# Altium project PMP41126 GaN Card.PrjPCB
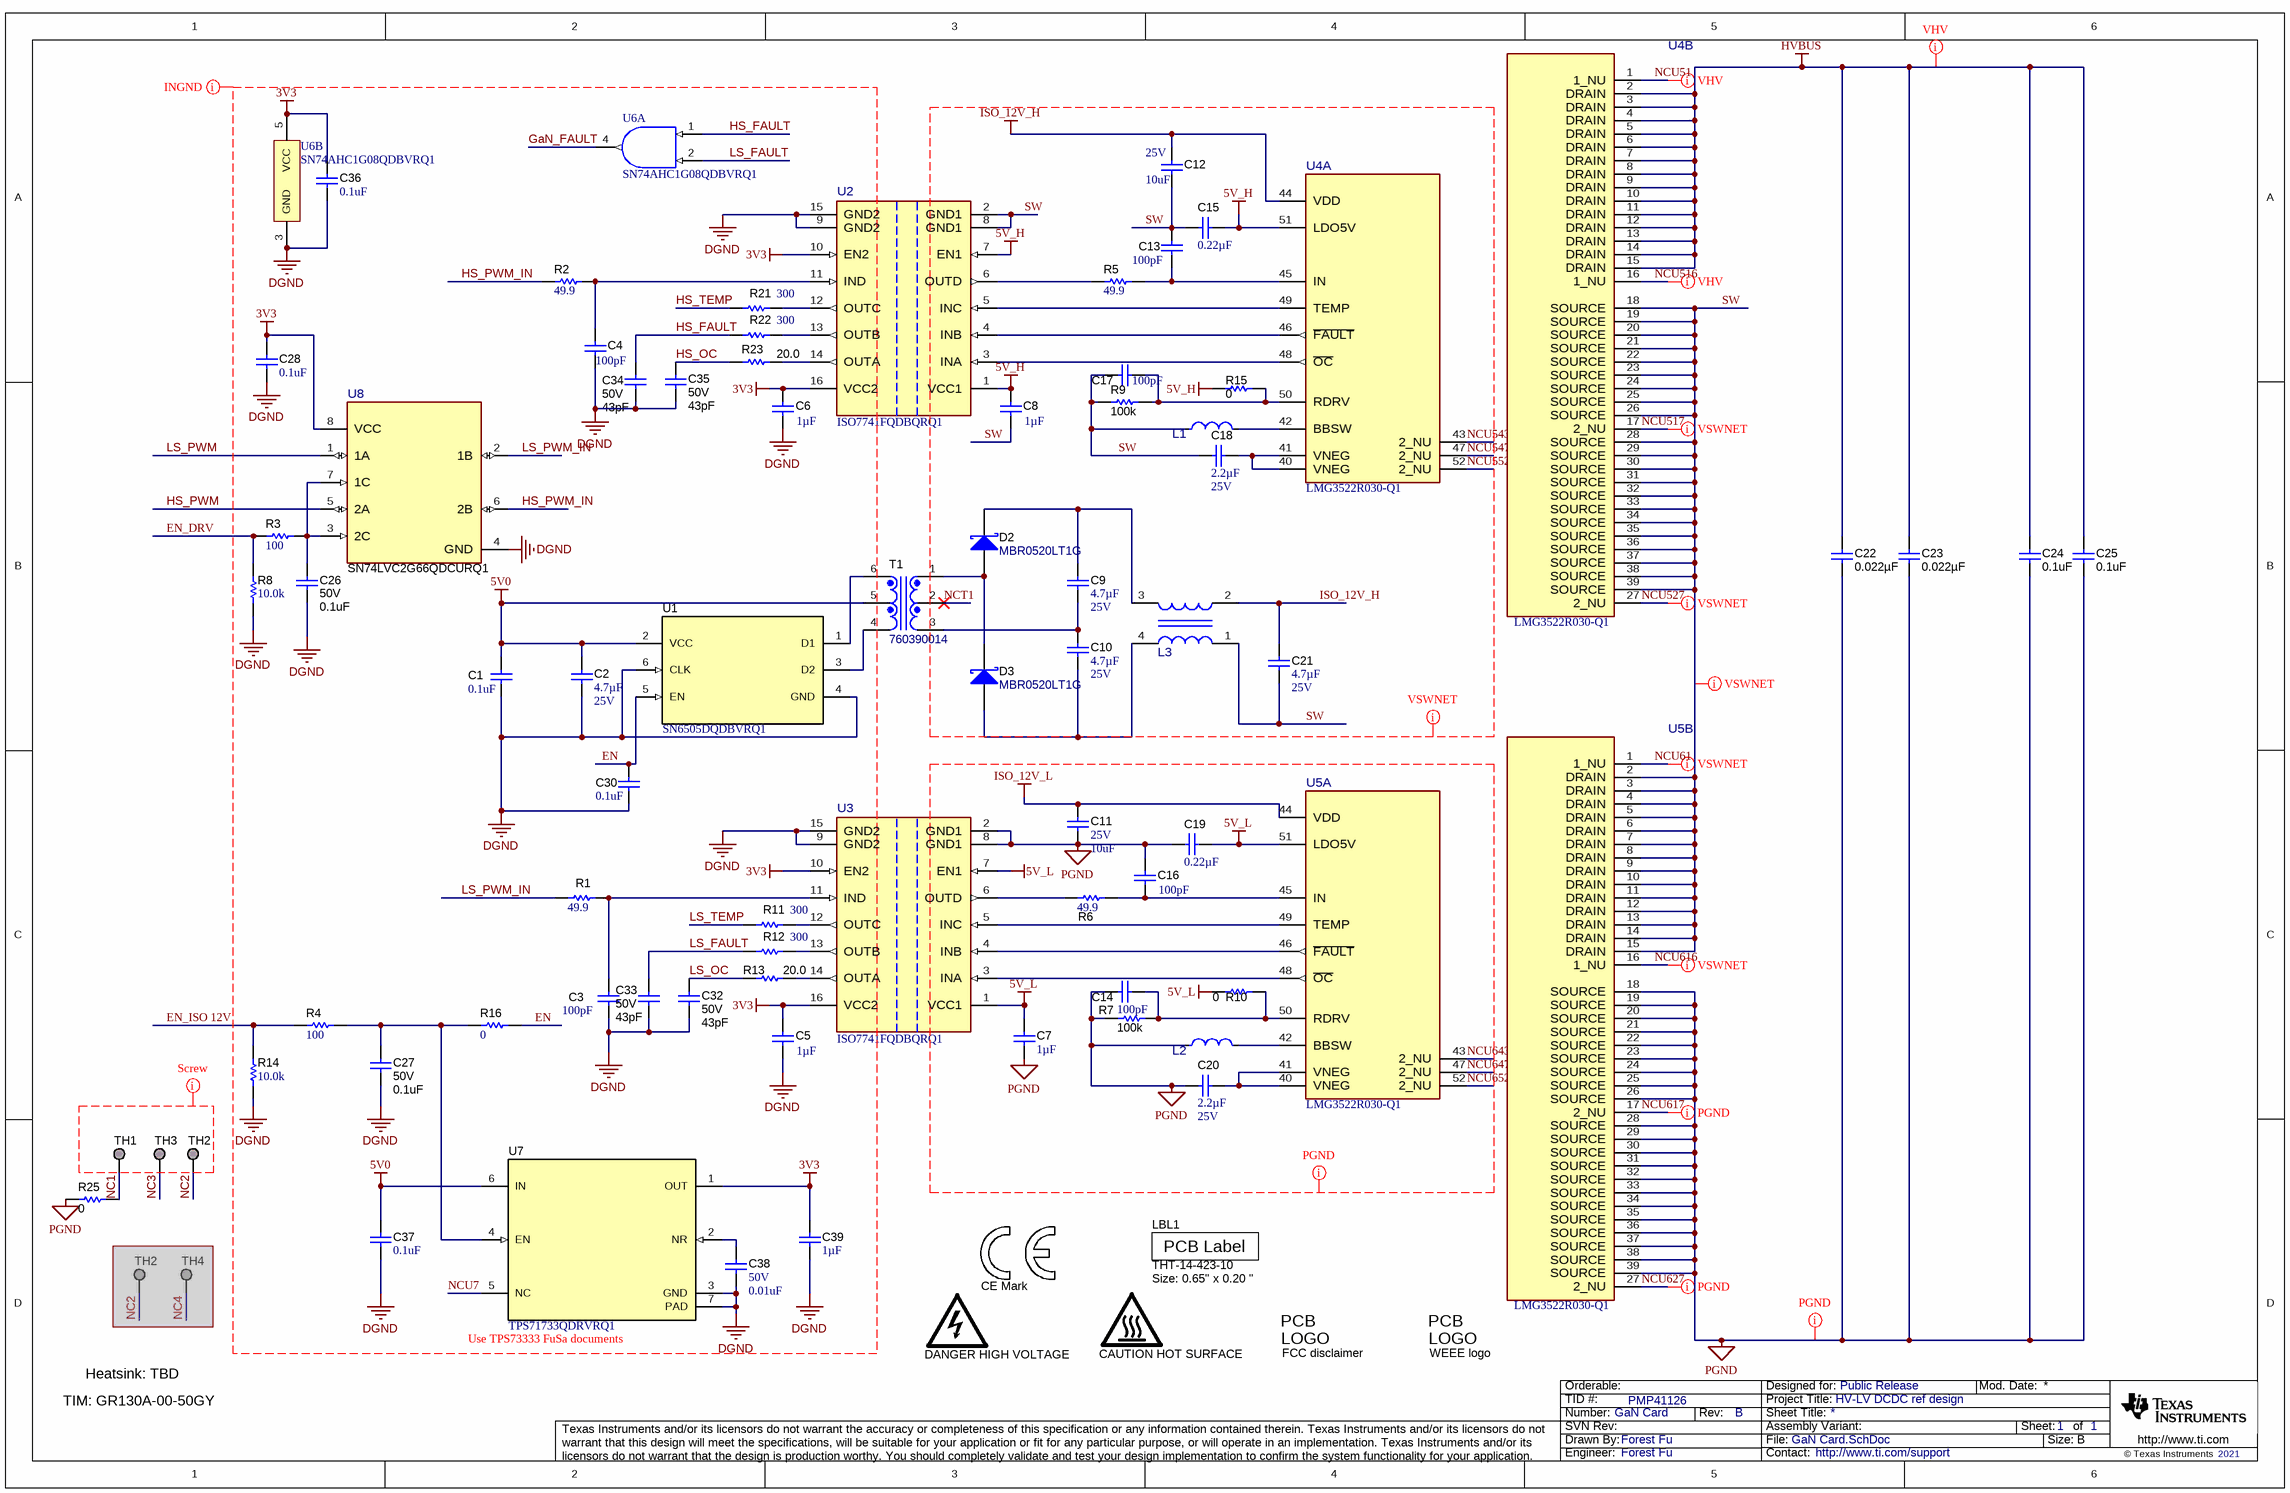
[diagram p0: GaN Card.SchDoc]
CopyrightYear: 2021; PCB_Layout: Forest Fu; PCB_Rev: B; PRJ_Customer: Public Release; PRJ_Engineer: Forest Fu; PRJ_Number: GaN Card; PRJ_Title: HV-LV DCDC ref design; SCH_Rev: B; TechSupport: http://www.ti.com/support; TID: PMP41126
2 sheets, 90 parts. Net scope: global (net labels, ports and power ports of the same name join across sheets).
Board file: GaN Card.PcbDoc
Sheets:
  GaN Card.SchDoc
  GaN Card_Hardware.SchDoc

## Sheet GaN Card.SchDoc
size 431 x 279 mm; DrawnBy: Forest Fu; SheetNumber: 1; SheetTotal: 1; PageSetup: Record=PageOptions¦CenterHorizontal=True¦CenterVertical=True¦PrintScale=1.00¦XCorrection=1.00¦YCorrection=1.00¦PrintKind=0¦BorderSize=5000000¦LeftOffset=0¦BottomOffset=0¦Orientation=2¦PaperLength=1000¦PaperWidth=1000¦Scale=100¦PaperSource=15¦PrintQuality=600¦MediaType=1¦DitherType=10¦PaperKind=Letter¦PrintScaleMode=1

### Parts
(Parts that share a designator on the sheet are numbered #1, #2 ... from top to bottom, then left to right.)
C1  ValueDisplayed: 0.1uF  [0402]  (hidden comment: GCM155R71H104KE02D)
C2  Cap_F: 4.7µF  VDC_V: 25V  [0805]  (hidden comment: CGA4J1X7R1E475K125AC)
C3  ValueDisplayed: 100pF  [0402]  (hidden comment: CGA2B2C0G1H101J050BA)
C4  ValueDisplayed: 100pF  [0402]  (hidden comment: CGA2B2C0G1H101J050BA)
C5  ValueDisplayed: 1µF  [0402]  (hidden comment: GRT155C71A105KE13D)
C6  ValueDisplayed: 1µF  [0402]  (hidden comment: GRT155C71A105KE13D)
C7  ValueDisplayed: 1µF  [0402]  (hidden comment: GRT155C71A105KE13D)
C8  ValueDisplayed: 1µF  [0402]  (hidden comment: GRT155C71A105KE13D)
C9  Cap_F: 4.7µF  VDC_V: 25V  [0805L]  (hidden comment: CGA4J1X7R1E475K125AC)
C10  Cap_F: 4.7µF  VDC_V: 25V  [0805L]  (hidden comment: CGA4J1X7R1E475K125AC)
C11  VDC_V: 25V  ValueDisplayed: 10uF  [1206_190]  (hidden comment: GCM31CC71E106KA03L)
C12  VDC_V: 25V  ValueDisplayed: 10uF  [1206_190]  (hidden comment: GCM31CC71E106KA03L)
C13  ValueDisplayed: 100pF  [0402]  (hidden comment: CGA2B2C0G1H101J050BA)
C14  ValueDisplayed: 100pF  [0402]  (hidden comment: CGA2B2C0G1H101J050BA)
C15  ValueDisplayed: 0.22µF  [0402]  (hidden comment: GCM155R71C224KE02D)
C16  ValueDisplayed: 100pF  [0402]  (hidden comment: CGA2B2C0G1H101J050BA)
C17  ValueDisplayed: 100pF  [0402]  (hidden comment: CGA2B2C0G1H101J050BA)
C18  Cap_F: 2.2µF  VDC_V: 25V  [0805_HV]  (hidden comment: GCM21BR71E225KA73L)
C19  ValueDisplayed: 0.22µF  [0402]  (hidden comment: GCM155R71C224KE02D)
C20  Cap_F: 2.2µF  VDC_V: 25V  [0805_HV]  (hidden comment: GCM21BR71E225KA73L)
C21  Cap_F: 4.7µF  VDC_V: 25V  [0805L]  (hidden comment: CGA4J1X7R1E475K125AC)
C22  ValueDisplayed: 0.022µF  [1206_190]  (hidden comment: C1206C223KDRACTU)
C23  ValueDisplayed: 0.022µF  [1206_190]  (hidden comment: C1206C223KDRACTU)
C24  ValueDisplayed: 0.1uF  [1812_254]  (hidden comment: C1812W104KDRACTU)
C25  ValueDisplayed: 0.1uF  [1812_254]  (hidden comment: C1812W104KDRACTU)
C26  VDC_V: 50V  ValueDisplayed: 0.1uF  [0402]  (hidden comment: GCM155R71H104KE02D)
C27  VDC_V: 50V  ValueDisplayed: 0.1uF  [0402]  (hidden comment: GCM155R71H104KE02D)
C28  ValueDisplayed: 0.1uF  [0402]  (hidden comment: GCM155R71H104KE02D)
C30  ValueDisplayed: 0.1uF  [0402]  (hidden comment: GCM155R71H104KE02D)
C32  VDC_V: 50V  ValueDisplayed: 43pF  [0402]  (hidden comment: GCQ1555C1H430JB01D)
C33  VDC_V: 50V  ValueDisplayed: 43pF  [0402]  (hidden comment: GCQ1555C1H430JB01D)
C34  VDC_V: 50V  ValueDisplayed: 43pF  [0402]  (hidden comment: GCQ1555C1H430JB01D)
C35  VDC_V: 50V  ValueDisplayed: 43pF  [0402]  (hidden comment: GCQ1555C1H430JB01D)
C36  ValueDisplayed: 0.1uF  [0402]  (hidden comment: GCM155R71H104KE02D)
C37  ValueDisplayed: 0.1uF  [0402]  (hidden comment: GCM155R71H104KE02D)
C38  VDC_V: 50V  ValueDisplayed: 0.01uF  [0402]  (hidden comment: CGA2B3X7R1H103K050BB)
C39  ValueDisplayed: 1µF  [0402]  (hidden comment: GRT155C71A105KE13D)
CAUTION_HOT_SURFACE  CAUTION HOT SURFACE  [IEC_HotSurface_Small]  (no BOM)
D2  MBR0520LT1G  [SOD-123]
D3  MBR0520LT1G  [SOD-123]
DANGER_HIGH_VOLTAGE  DANGER HIGH VOLTAGE  [IEC_HighVoltage_Small]  (no BOM)
L1  SDEM20161T-4R7MS  [FP-SDEM20161T-4R7MS_SMD2-MFG]  (value not drawn)
L2  SDEM20161T-4R7MS  [FP-SDEM20161T-4R7MS_SMD2-MFG]  (value not drawn)
L3  ACT32P-102-2P-TL01  [FP-ACT32P-102-2P-TL01_SMT4_3MM9_2MM5-MFG]  (value not drawn)
LBL1  THT-14-423-10  Note: Size: 0.65" x 0.20 "  [Label_650x200]
Logo1  CE Mark  [CE_Mark_5mm]  (no BOM)
Logo3  FCC disclaimer  [FCC_disclaimer]  (no BOM)
Logo4  WEEE logo  [WEEE_Minimum]  (no BOM)
R1  ValueDisplayed: 49.9  [0402]  (hidden comment: CRCW040249R9FKED)
R2  ValueDisplayed: 49.9  [0402]  (hidden comment: CRCW040249R9FKED)
R3  ValueDisplayed: 100  [0402]  (hidden comment: CRCW0402100RFKED)
R4  ValueDisplayed: 100  [0402]  (hidden comment: CRCW0402100RFKED)
R5  ValueDisplayed: 49.9  [0402]  (hidden comment: CRCW040249R9FKED)
R6  ValueDisplayed: 49.9  [0402]  (hidden comment: CRCW040249R9FKED)
R7  ValueDisplayed: 100k  [0402]  (hidden comment: CRCW0402100KFKED)
R8  ValueDisplayed: 10.0k  [0402]  (hidden comment: MCS0402MD1002BE100)
R9  ValueDisplayed: 100k  [0402]  (hidden comment: CRCW0402100KFKED)
R10  ValueDisplayed: 0  [0402]  (hidden comment: ERJ-2GE0R00X)
R11  ValueDisplayed: 300  [0402]  (hidden comment: CRCW0402300RJNED)
R12  ValueDisplayed: 300  [0402]  (hidden comment: CRCW0402300RJNED)
R13  ValueDisplayed: 20.0  [0402]  (hidden comment: CRCW040220R0FKED)
R14  ValueDisplayed: 10.0k  [0402]  (hidden comment: MCS0402MD1002BE100)
R15  ValueDisplayed: 0  [0402]  (hidden comment: ERJ-2GE0R00X)
R16  ValueDisplayed: 0  [0402]  (hidden comment: CRCW04020000Z0EDHP)
R21  ValueDisplayed: 300  [0402]  (hidden comment: CRCW0402300RJNED)
R22  ValueDisplayed: 300  [0402]  (hidden comment: CRCW0402300RJNED)
R23  ValueDisplayed: 20.0  [0402]  (hidden comment: CRCW040220R0FKED)
R25  ValueDisplayed: 0  [1206]  (hidden comment: CRCW12060000Z0EA)
T1  760390014  [Wurth_760390013]
TH1  (no value)  [TP_H045P075]  (no BOM)
TH2#1  (no value)  [TP_H045P075]  (no BOM)
TH2#2  (no value)  [TP_H045P075]  (no BOM)  (masked out: inside a compile mask, not in the netlist)
TH3  (no value)  [TP_H045P075]  (no BOM)
TH4  (no value)  [TP_H045P075]  (no BOM)  (masked out: inside a compile mask, not in the netlist)
U1  SN6505DQDBVRQ1  [DBV0006A_N]
U2  ISO7741FQDBQRQ1  [DBQ0016A-MFG]
U3  ISO7741FQDBQRQ1  [DBQ0016A-MFG]
U4  LMG3522R030-Q1  [RQS0052C-C01-MFG]  (parts A,B of 2)
U5  LMG3522R030-Q1  [RQS0052C-C01-MFG]  (parts A,B of 2)
U6  SN74AHC1G08QDBVRQ1  [DBV0005A_N]  (parts A,B of 2)
U7  TPS71733QDRVRQ1  [DRV0006A]
U8  SN74LVC2G66QDCURQ1  [DCU0008A-MFG]

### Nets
3V3: C5.1 C6.1 C28.1 C36.1 C39.1 U2.10(EN2) U2.16(VCC2) U3.10(EN2) U3.16(VCC2) U6.5(VCC) U7.1(OUT) U8.8(VCC)
5V0: C1.1 C2.1 C37.1 T1.5 U1.2(VCC) U7.6(IN)
5V_H: C8.1 C15.2 R15.1 U2.1(VCC1) U2.7(EN1) U4.51(LDO5V)
5V_L: C7.2 C19.2 R10.1 U3.1(VCC1) U3.7(EN1) U5.51(LDO5V)
DGND: C1.2 C2.2 C3.2 C4.2 C5.2 C6.2 C26.2 C27.2 C28.2 C30.2 C32.2 C33.2 C34.2 C35.2 C36.2 C37.2 C38.2 C39.2 R8.1 R14.1 U1.4(GND) U1.6(CLK) U2.9(GND2) U2.15(GND2) U3.9(GND2) U3.15(GND2) U6.3(GND) U7.3(GND) U7.7(PAD) U8.4(GND)
HVBUS: C22.1 C23.1 C24.1 C25.1 U4.2(DRAIN) U4.3(DRAIN) U4.4(DRAIN) U4.5(DRAIN) U4.6(DRAIN) U4.7(DRAIN) U4.8(DRAIN) U4.9(DRAIN) U4.10(DRAIN) U4.11(DRAIN) U4.12(DRAIN) U4.13(DRAIN) U4.14(DRAIN) U4.15(DRAIN)
ISO_12V_H: C12.1 C21.1 L3.2 U4.44(VDD)
ISO_12V_L: C11.1 U5.44(VDD)
PGND: C7.1 C11.2 C14.1 C16.1 C19.1 C20.2 C22.2 C23.2 C24.2 C25.2 L2.1 R7.1 R25.1 U3.2(GND1) U3.8(GND1) U5.18(SOURCE) U5.19(SOURCE) U5.20(SOURCE) U5.21(SOURCE) U5.22(SOURCE) U5.23(SOURCE) U5.24(SOURCE) U5.25(SOURCE) U5.26(SOURCE) U5.28(SOURCE) U5.29(SOURCE) U5.30(SOURCE) U5.31(SOURCE) U5.32(SOURCE) U5.33(SOURCE) U5.34(SOURCE) U5.35(SOURCE) U5.36(SOURCE) U5.37(SOURCE) U5.38(SOURCE) U5.39(SOURCE)
EN: C30.1 R16.2 U1.5(EN)
EN_DRV: R3.1 R8.2
EN_ISO 12V: R4.1 R14.2
GaN_FAULT: U6.4(Y)
HS_FAULT: C34.1 R22.2 U6.1(A)
HS_OC: C35.1 R23.2
HS_PWM: U8.5(2A)
HS_PWM_IN: R2.1 U8.6(2B)
HS_TEMP: R21.2
LS_FAULT: C33.1 R12.2 U6.2(B)
LS_OC: C32.1 R13.2
LS_PWM: U8.1(1A)
LS_PWM_IN: R1.1 U8.2(1B)
LS_TEMP: R11.2
NC1: R25.2 TH1.1
NC2: TH2#1.1
NC3: TH3.1
NCT1: T1.2
NCU7: U7.5(NC)
NCU51: U4.1(1_NU)
NCU61: U5.1(1_NU)
NCU516: U4.16(1_NU)
NCU517: U4.17(2_NU)
NCU527: U4.27(2_NU)
NCU543: U4.43(2_NU)
NCU547: U4.47(2_NU)
NCU552: U4.52(2_NU)
NCU616: U5.16(1_NU)
NCU617: U5.17(2_NU)
NCU627: U5.27(2_NU)
NCU643: U5.43(2_NU)
NCU647: U5.47(2_NU)
NCU652: U5.52(2_NU)
SW: C8.2 C12.2 C13.1 C15.1 C17.1 C18.2 C21.2 L1.1 L3.1 R9.1 U2.2(GND1) U2.8(GND1) U4.18(SOURCE) U4.19(SOURCE) U4.20(SOURCE) U4.21(SOURCE) U4.22(SOURCE) U4.23(SOURCE) U4.24(SOURCE) U4.25(SOURCE) U4.26(SOURCE) U4.28(SOURCE) U4.29(SOURCE) U4.30(SOURCE) U4.31(SOURCE) U4.32(SOURCE) U4.33(SOURCE) U4.34(SOURCE) U4.35(SOURCE) U4.36(SOURCE) U4.37(SOURCE) U4.38(SOURCE) U4.39(SOURCE) U5.2(DRAIN) U5.3(DRAIN) U5.4(DRAIN) U5.5(DRAIN) U5.6(DRAIN) U5.7(DRAIN) U5.8(DRAIN) U5.9(DRAIN) U5.10(DRAIN) U5.11(DRAIN) U5.12(DRAIN) U5.13(DRAIN) U5.14(DRAIN) U5.15(DRAIN)
NetC3_1: C3.1 R1.2 U3.11(IND)
NetC4_1: C4.1 R2.2 U2.11(IND)
NetC9_1: C9.1 D2.1(K) L3.3
NetC9_2: C9.2 C10.1 T1.3
NetC10_2: C10.2 D3.2(A) L3.4
NetC13_2: C13.2 R5.1 U4.45(IN)
NetC14_2: C14.2 R7.2 R10.2 U5.50(RDRV)
NetC16_2: C16.2 R6.2 U5.45(IN)
NetC17_2: C17.2 R9.2 R15.2 U4.50(RDRV)
NetC18_1: C18.1 U4.40(VNEG) U4.41(VNEG)
NetC20_1: C20.1 U5.40(VNEG) U5.41(VNEG)
NetC26_1: C26.1 R3.2 U8.3(2C) U8.7(1C)
NetC27_1: C27.1 R4.2 R16.1 U7.4(EN)
NetC38_1: C38.1 U7.2(NR)
NetD2_2: D2.2(A) D3.1(K) T1.1
NetL1_2: L1.2 U4.42(BBSW)
NetL2_2: L2.2 U5.42(BBSW)
NetR5_2: R5.2 U2.6(OUTD)
NetR6_1: R6.1 U3.6(OUTD)
NetR11_1: R11.1 U3.12(OUTC)
NetR12_1: R12.1 U3.13(OUTB)
NetR13_1: R13.1 U3.14(OUTA)
NetR21_1: R21.1 U2.12(OUTC)
NetR22_1: R22.1 U2.13(OUTB)
NetR23_1: R23.1 U2.14(OUTA)
NetT1_4: T1.4 U1.3(D2)
NetT1_6: T1.6 U1.1(D1)
NetU2_3: U2.3(INA) U4.48(~{OC})
NetU2_4: U2.4(INB) U4.46(~{FAULT})
NetU2_5: U2.5(INC) U4.49(TEMP)
NetU3_3: U3.3(INA) U5.48(~{OC})
NetU3_4: U3.4(INB) U5.46(~{FAULT})
NetU3_5: U3.5(INC) U5.49(TEMP)

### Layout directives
net class INGND: 3V3, 5V0, DGND, EN, GaN_FAULT, HS_FAULT, HS_OC, HS_PWM_IN, HS_TEMP, LS_FAULT, LS_OC, LS_PWM_IN, LS_TEMP, NCU7
net class VSWNET: 5V_H, ISO_12V_H, NCT1, NCU61, NCU517, NCU527, NCU543, NCU547, NCU552, NCU616, SW
net class PGND: 5V_L, ISO_12V_L, NCU617, NCU627, NCU643, NCU647, NCU652, PGND
net class Screw: (no net found under the mark)
net class VHV: HVBUS, NCU51, NCU516

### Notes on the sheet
- Heatsink: TBD
- (near U7) Use TPS73333 FuSa documents
- TIM: GR130A-00-50GY

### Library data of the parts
C1 C28 C30 C36 C37 = CMP-0006356-2: CAP, CERM, 0.1 uF, 50 V, +/- 10%, X7R, AEC-Q200 Grade 1, 0402; Manufacturer: MuRata; Polarized: N; Value: 0.1uF; U/M: EA; Cap_F: 100nF; Value1: Unknown; VDC_V: 50V; TaMin_C: -55°C; TaMax_C: 125°C; SizeArea_mm2: 0.5; SizeAreaWB_mm2: 3; SizeX_mm: 1; SizeZ_mm: 0.6; AEC Category: Q200; AEC Qualified: Y
C2 C9 C10 C21 = CMP-0076706-1: CAP, CERM, 4.7 µF, 25 V,+/- 10%, X7R, AEC-Q200 Grade 1, 0805; Manufacturer: TDK; SizeAreaWB_mm2: 6.75; SizeArea_mm2: 2.5; AEC Qualified: Y; AEC Category: Q200; Value: 4.7uF; TaMax_C: 125°C; SizeZ_mm: 1.45; AEC Grade: 1; Polarized: N; TaMin_C: -55°C; SizeY_mm: 1.25; U/M: EA; SizeX_mm: 2.0; Cap_Case: 2x1.25x1.25mm
C3 C4 C13 C14 C16 C17 = CMP-0006308-2: CAP, CERM, 100 pF, 50 V, +/- 5%, C0G/NP0, AEC-Q200 Grade 1, 0402; Manufacturer: TDK; TaMin_C: -55°C; Polarized: N; SizeAreaWB_mm2: 3; Value1: Unknown; U/M: EA; Value: 100pF; TaMax_C: 125°C; SizeZ_mm: 0.6; SizeX_mm: 1; SizeY_mm: 0.5; Value2: 50V; CompType: Capacitor; AEC Qualified: Y; AEC Category: Q200
C5-C8 C39 = CMP-0085818-1: CAP, CERM, 1 µF, 10 V,+/- 10%, X7S, AEC-Q200 Grade 1, 0402; Manufacturer: MuRata; TaMin_C: -55°C; Polarized: N; SizeAreaWB_mm2: 3; U/M: EA; Value: 1uF; TaMax_C: 125°C; SizeZ_mm: 0.6; SizeX_mm: 1; SizeY_mm: 0.5; Value2: 10V; AEC Qualified: Y; AEC Category: Q200
C11 C12 = CMP-0008807-2: CAP, CERM, 10 uF, 25 V, +/- 10%, X7S, AEC-Q200 Grade 1, 1206_190; Manufacturer: MuRata; TaMin_C: -55°C; Polarized: N; SizeAreaWB_mm2: 10.92; Value1: Unknown; U/M: EA; Value: 10uF; TaMax_C: 125°C; SizeZ_mm: 1.9; SizeX_mm: 3.2; SizeY_mm: 1.6; Cap_Case: 1206; SizeArea_mm2: 5.12; AEC Qualified: Y; Cap_F: 10µF; AEC Grade: 1; AEC Category: Q200
C15 C19 = CMP-0078265-1: CAP, CERM, 0.22 µF, 16 V,+/- 10%, X7R, AEC-Q200 Grade 1, 0402; Manufacturer: MuRata; SizeX_mm: 1; TaMin_C: -55°C; SizeArea_mm2: 0.5; TaMax_C: 125°C; U/M: EA; SizeAreaWB_mm2: 3; VDC_V: 16V; AEC Qualified: Y; SizeZ_mm: 0.6; Polarized: N; AEC Category: Q200; Cap_F: 220nF; Value: 0.22uF
C18 C20 = CMP-0083622-1: CAP, CERM, 2.2 µF, 25 V,+/- 10%, X7R, AEC-Q200 Grade 1, 0805; Manufacturer: MuRata; TaMin_C: -55°C; Polarized: N; SizeAreaWB_mm2: 6.75; U/M: EA; Value: 2.2uF; TaMax_C: 125°C; SizeZ_mm: 1.45; SizeX_mm: 2; SizeY_mm: 1.25; Cap_Case: 0805; SizeArea_mm2: 2.5; AEC Qualified: Y; AEC Grade: 1; AEC Category: Q200
C22 C23 = CMP-0084048-1: CAP, CERM, 0.022 µF, 1000 V,+/- 10%, X7R, AEC-Q200 Grade 1, 1206; Manufacturer: Kemet; Polarized: N; CompType: Capacitor; Value: 0.022uF; U/M: EA; Cap_F: 22nF; VDC_V: 1kV; Value2: 1000V; TaMin_C: -55°C; TaMax_C: 125°C; Cap_Case: 1206; SizeArea_mm2: 5.12; SizeAreaWB_mm2: 10.92; SizeX_mm: 3.2; SizeY_mm: 1.6; SizeZ_mm: 1.9; AEC Category: Q200; AEC Qualified: Y; AEC Grade: 1
C24 C25 = CMP-0009326-2: CAP, CERM, 0.1 uF, 1000 V, +/- 10%, X7R, 1812; Manufacturer: Kemet; Polarized: N; Value: 0.1uF; U/M: EA; Cap_F: 100nF; Value1: Unknown; VDC_V: 1kV; Value2: 1000V; TaMin_C: -55°C; TaMax_C: 125°C; Cap_Case: 1812; AEC Category: Q200; SizeArea_mm2: 14.4; SizeAreaWB_mm2: 23.1; SizeX_mm: 4.5; SizeY_mm: 3.2; SizeZ_mm: 2.54
C26 C27 = CMP-0006356-1: CAP, CERM, 0.1 uF, 50 V, +/- 10%, X7R, AEC-Q200 Grade 1, 0402; Manufacturer: MuRata; TaMin_C: -55°C; Polarized: N; SizeAreaWB_mm2: 3; Value1: Unknown; U/M: EA; Value: 0.1uF; TaMax_C: 125°C; SizeZ_mm: 0.6; SizeX_mm: 1; SizeY_mm: 0.5; AEC Qualified: Y; Cap_F: 100nF; AEC Category: Q200
C32-C35 = CMP-0860835-1: CAP, CERM, 43 pF, 50 V,+/- 5%, C0G/NP0, AEC-Q200 Grade 1, 0402; Manufacturer: MuRata; SizeY_mm: 0.5; SizeZ_mm: 0.6; AEC Qualified: Y; AEC Grade: 1; AEC Category: Q200; U/M: EA; Value: 43pF; Polarized: N; TaMin_C: -55°C; SizeAreaWB_mm2: 3; TaMax_C: 125°C
C38 = CMP-0006324-2: CAP, CERM, 0.01 uF, 50 V, +/- 10%, X7R, AEC-Q200 Grade 1, 0402; Manufacturer: TDK; TaMin_C: -55°C; ESR_ohm: 3.33065d; Polarized: N; SizeAreaWB_mm2: 3; Value1: 0.333065 ohm; U/M: EA; Value: 0.01uF; TaMax_C: 125°C; SizeZ_mm: 0.6; SizeX_mm: 1; SizeY_mm: 0.5; AEC Qualified: Y; Cap_F: 10nF; IRMS_A: 3.23373dA; AEC Category: Q200
CAUTION_HOT_SURFACE = CMP-0074837-1: IEC 61010-1 Hot Surface Warning; Library Reference: IEC_HotSurface; SymbolCreator: a0412235
D2 D3 = CMP-0028524-2: Diode, Schottky, 20 V, 0.5 A, SOD-123; Manufacturer: ON Semiconductor; Green_REACh: Passed; TJmax_C: 125°C; Value1: 0.5A; SizeZ_mm: 1.35; Value2: 0.385V; Vf_V: 385mV; AEC Category: Q101; SizeY_mm: 1.7; Value: 20V; Io_A: 500mA; SizeX_mm: 3.85; Green_Lifecycle: Active; RJC_CperW: 150; SizeAreaWB_mm2: 13.095; SizeArea_mm2: 6.545
DANGER_HIGH_VOLTAGE = CMP-0074835-1: IEC 61010-1 High Voltage Warning; Library Reference: IEC_HighVoltage; SymbolCreator: a0412235
L1 L2 = CMP-0089347-1: 4.7µH Unshielded Inductor 1.1A 426mOhm Max 0806 (2016 Metric); Manufacturer: Cyntec; AEC Qualified: No; Material: Metal Dust; Isat: 1.26A; Test Frequency: 1MHz; DCR_ohm: 0.426; SizeZ_mm: 1mm; Tolerance_%: 20%
L3 = CMP-0001686-1: 2 Line Common Mode Choke Surface Mount 1 kOhms @ 100 MHz 800mA DCR 150mOhm; Manufacturer: TDK; AEC Grade: Grade 0; AEC Qualified: Yes; DCR_ohm: 0.15; SizeZ_mm: 2.5mm; Impedance At Frequency: 1000Ω @ 100MHz; Tolerance_%: +30/-20%
LBL1 = CMP-0003625-1: Thermal Transfer Printable Labels, 0.650" W x 0.200" H - 10,000 per roll; Manufacturer: Brady; CompType: Label
Logo1 = CMP-0074844-1: SymbolCreator: a0412235
Logo3 = CMP-0074847-1: FCC_disclaimer; Library Reference: Logo
Logo4 = CMP-0074769-1
R1 R2 R5 R6 = CMP-0026404-2: RES, 49.9, 1%, 0.063 W, AEC-Q200 Grade 0, 0402; Manufacturer: Vishay-Dale; Value: 49.9; Value_Code: 49R9; Power_W: 63mW; Value2: 0.063W; VDC_V: 50V; TempCo: 100 ppm/C; EIA_Code: E96; AEC Category: Q200; AEC Qualified: Y; AEC Grade: 0; SizeArea_mm2: 0.5; SizeX_mm: 1; SizeZ_mm: 0.6
R3 R4 = CMP-0025951-3: RES, 100, 1%, 0.063 W, AEC-Q200 Grade 0, 0402; Manufacturer: Vishay-Dale; Power_W: 63mW; TempCo: 100 ppm/C; Value_Code: 100R; Value: 100; EIA_Code: E96; SizeX_mm: 1; SizeY_mm: 0.5; SizeZ_mm: 0.6; Value2: 0.063W; AEC Qualified: Y; VDC_V: 50V; AEC Category: Q200; AEC Grade: 0
R7 R9 = CMP-0025950-3: RES, 100 k, 1%, 0.063 W, AEC-Q200 Grade 0, 0402; Manufacturer: Vishay-Dale; Power_W: 63mW; TempCo: 100 ppm/C; Value: 100k; EIA_Code: E96; SizeX_mm: 1; SizeY_mm: 0.5; SizeZ_mm: 0.6; Value2: 0.063W; AEC Qualified: Y; VDC_V: 50V; AEC Category: Q200; AEC Grade: 0
R8 R14 = CMP-0077124-1: RES, 10.0 k, 0.1%, 0.1 W, AEC-Q200 Grade 0, 0402; Manufacturer: Vishay/Beyschlag; Value_Code: 10k0; SizeArea_mm2: 0.5; AEC Qualified: Y; AEC Category: Q200; Res_ohm: 10k; Value: 10.0k; SizeZ_mm: 0.6; EIA_Code: E192; TempCo: 25 ppm/C; AEC Grade: 0; Power_W: 100mW; VDC_V: 50V; Value2: 0.1W; U/M: EA; SizeX_mm: 1.0
R10 R15 = CMP-0026992-3: RES, 0, 5%, 0.1 W, AEC-Q200 Grade 0, 0402; Manufacturer: Panasonic; Power_W: 100mW; TempCo: 600 ppm/C; Value_Code: 0000; Value: 0; EIA_Code: E24; SizeX_mm: 1; SizeY_mm: 0.5; SizeZ_mm: 0.6; Value2: 0.1W; CompType: Resistor; AEC Qualified: Y; VDC_V: 50V; AEC Category: Q200; SizeAreaWB_mm2: 3
R11 R12 R21 R22 = CMP-0026902-3: RES, 300, 5%, 0.063 W, AEC-Q200 Grade 0, 0402; Manufacturer: Vishay-Dale; Power_W: 63mW; TempCo: 200 ppm/C; Value_Code: 300R; Value: 300; EIA_Code: E24; SizeX_mm: 1; SizeY_mm: 0.5; SizeZ_mm: 0.6; Value2: 0.063W; AEC Qualified: Y; VDC_V: 50V; AEC Category: Q200; AEC Grade: 0
R13 R23 = CMP-0026164-2: RES, 20.0, 1%, 0.063 W, AEC-Q200 Grade 0, 0402; Manufacturer: Vishay-Dale; Power_W: 63mW; TempCo: 100 ppm/C; Value_Code: 20R0; Value: 20.0; EIA_Code: E96; Res_ohm: 20; SizeX_mm: 1; SizeY_mm: 0.5; SizeZ_mm: 0.6; Value2: 0.063W; CompType: Resistor; AEC Qualified: Y; VDC_V: 50V; AEC Category: Q200; AEC Grade: 0
R16 = CMP-0081856-1: RES, 0, 0%, 0.2 W, AEC-Q200 Grade 0, 0402; Manufacturer: Vishay-Dale; SizeAreaWB_mm2: 3; SizeArea_mm2: 0.5; AEC Qualified: Y; AEC Category: Q200; Value: 0; SizeZ_mm: 0.6; Power_W: 200mW; VDC_V: 50V; Value2: 0.2W; SizeX_mm: 1
R25 = CMP-0018573-3: RES, 0, 5%, 0.25 W, AEC-Q200 Grade 0, 1206; Manufacturer: Vishay-Dale; Power_W: 250mW; TempCo: 200 ppm/C; Value_Code: 0000; Value: 0; EIA_Code: E24; SizeX_mm: 3.2; SizeY_mm: 1.6; SizeZ_mm: 1.35; Value2: 0.25W; SizeArea_mm2: 5.12; AEC Qualified: Y; VDC_V: 200V; AEC Category: Q200
T1 = CMP-0030718-1: Transformer, 475uH, SMT; Manufacturer: Wurth Elektronik; DCR_ohm: 0.31; Lp: 475; Ind_H: 475µH
TH1 TH2#1 TH2#2 TH3 TH4 = CMP-0003719-1: Testpoint; Manufacturer: Texas Instruments; Key: TP_H0.45P0.75; CompType: Pad
U1 = CMP-0860735-1: SN6505DQDBVRQ1, DBV0006A (SOT-23-6); Alternate PartNumber: SN6505DQDBVTQ1; Alternate Manufacturer: Texas Instruments; CompType: IC; SizeAreaWB_mm2: 14.82; SizeArea_mm2: 8.12; SizeZ_mm: 1.45; SizeY_mm: 2.9; SizeX_mm: 2.8; AEC Category: Q200
U2 U3 = CMP-0090469-1: General Purpose Digital Isolator 2500Vrms 4 Channel 100Mbps 85kV/µs CMTI 16-SSOP (0.154", 3.90mm Width); Manufacturer: Texas Instruments; TaMin_C: -40°C; TaMax_C: +125°C; TJmax_C: +150°C; AEC Grade: Grade 1; Min Supply Voltage: 2.25V; AEC Qualified: Yes; Max Supply Voltage: 5.5V; Standoff Height: 0.11mm; Nominal Supply Current: 1.5-18mA; SizeZ_mm: 1.75mm
U4 U5 = CMP-0094891-1: 650-V 30-mΩ GaN FET with Integrated Driver, Protection, and Temperature Reporting; Manufacturer: Texas Instruments; Max Supply Voltage: 18V; TaMax_C: +125°C; TaMin_C: -40°C; Nominal Supply Current: 16mA; Number Of Outputs: 1; Standoff Height: 0mm; Min Supply Voltage: 7.5V; TJmax_C: +150°C; AEC Grade: Grade 1; SizeZ_mm: 1mm; Output Voltage: 520V; AEC Qualified: Yes
U6 = CMP-0051573-2: Automotive Catalog Single 2-Input Positive-AND Gate, DBV0005A (SOT-23-5); Generic Part Number: SN74AHC1G08-Q1; Manufacturer: Texas Instruments; Output Drive (IOL/IOH)(Max)(mA): 50/-50; Output Type: CMOS; Logic: True; Bits(#): 1; Schmitt Trigger: No; VCC(Max)(V): 5.5; Gate Type: AND; VCC(Min)(V): 2; Voltage(Nom)(V): 3.3,5; tpd @ Nom Voltage(Max)(ns): 12.3,7.9; F @ Nom Voltage(Max)(Mhz): 75; ICC @ Nom Voltage(Max)(mA): 0.01; AEC Category: Q200; AEC Qualified: Y; CompType: IC; SizeAreaWB_mm2: 14.82; SizeArea_mm2: 8.12; SizeX_mm: 2.8; SizeY_mm: 2.9; SizeZ_mm: 1.45
U7 = CMP-0082417-1: Low Noise, High-Bandwidth PSRR Low-Dropout 150mA Linear Regulator for Automotive Applications, DRV0006A (WSON-6); Alternate Manufacturer: Texas Instruments; SizeAreaWB_mm2: 9; SizeZ_mm: 0.8; SizeX_mm: 2; SizeArea_mm2: 4; CompType: IC; AEC Qualified: Y; AEC Category: Q200
U8 = CMP-0121233-1: Automotive Dual Bilateral Analog Switch; Manufacturer: Texas Instruments; SizeZ_mm: 0.9mm; AEC Qualified: Yes; -3Db Bandwith: 300MHz; AEC Grade: Grade 1; Max Supply Voltage: 5.5V; Min Supply Voltage: 1.65V; Mux Demux Ratio: 1:1; Nominal Supply Current: 1-15uA; On State Resistance: 6Ω; PositionCount: 2; Standoff Height: 0mm; TaMax_C: +125°C; TaMin_C: -40°C; TJmax_C: +150°C

## Sheet GaN Card_Hardware.SchDoc
size 431 x 279 mm; Date: Not shown in title block; ApprovedBy: Not shown in title block; CheckedBy: Not shown in title block; Author: Not shown in title block; CompanyName: Not shown in title block; DrawnBy: Forest Fu; Engineer: Not shown in title block; Organization: Not shown in title block; Address1: Not shown in title block; Address2: Not shown in title block; Address3: Not shown in title block; Address4: Not shown in title block; DocumentNumber: 1; Revision: Use project parameter SCH_Rev; SheetNumber: 1; SheetTotal: 1; PageSetup: Record=PageOptions¦CenterHorizontal=True¦CenterVertical=True¦PrintScale=1.00¦XCorrection=1.00¦YCorrection=1.00¦PrintKind=0¦BorderSize=5000000¦LeftOffset=0¦BottomOffset=0¦Orientation=2¦PaperLength=1000¦PaperWidth=1000¦Scale=100¦PaperSource=15¦PrintQuality=600¦MediaType=1¦DitherType=10¦PaperKind=Letter¦PrintScaleMode=1
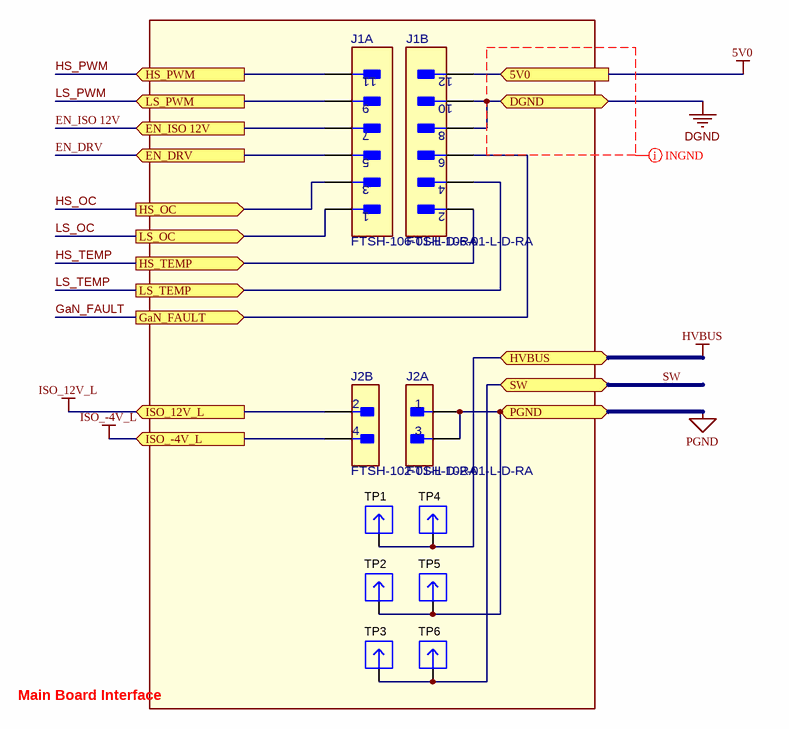
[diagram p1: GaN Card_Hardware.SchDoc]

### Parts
J1  FTSH-106-01-L-D-RA  [FP-FTSH-106-01-L-D-RA_HDR12-MFG]  (parts A,B of 2)
J2  FTSH-102-01-L-D-RA  [FP-FTSH-102-01-L-D-RA_HDR4-MFG]  (parts A,B of 2)
TP1  3621-0-32-15-00-00-08-0  [Mill-Max_3621-0-32-xx-00-00-08-0]  (value not drawn)
TP2  3621-0-32-15-00-00-08-0  [Mill-Max_3621-0-32-xx-00-00-08-0]  (value not drawn)
TP3  3621-0-32-15-00-00-08-0  [Mill-Max_3621-0-32-xx-00-00-08-0]  (value not drawn)
TP4  3621-0-32-15-00-00-08-0  [Mill-Max_3621-0-32-xx-00-00-08-0]  (value not drawn)
TP5  3621-0-32-15-00-00-08-0  [Mill-Max_3621-0-32-xx-00-00-08-0]  (value not drawn)
TP6  3621-0-32-15-00-00-08-0  [Mill-Max_3621-0-32-xx-00-00-08-0]  (value not drawn)

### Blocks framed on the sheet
Main Board Interface: J1 J2 TP1-TP6

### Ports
5V0 (in), DGND (bidir), EN_DRV (in), EN_ISO 12V (in), GaN_FAULT (out), HS_OC (out), HS_PWM (in), HS_TEMP (out), HVBUS (bidir), ISO_12V_L (in), ISO_-4V_L (in), LS_OC (out), LS_PWM (in), LS_TEMP (out), PGND (bidir), SW (bidir)

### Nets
5V0: J1.12 ; port 5V0
DGND: J1.8 J1.10 ; port DGND
HVBUS: TP1.1 TP4.1 ; port HVBUS
ISO_12V_L: J2.2 ; port ISO_12V_L
ISO_-4V_L: J2.4 ; port ISO_-4V_L
PGND: J2.1 J2.3 TP2.1 TP5.1 ; port PGND
EN_DRV: J1.5 ; port EN_DRV
EN_ISO 12V: J1.7 ; port EN_ISO 12V
GaN_FAULT: J1.6 ; port GaN_FAULT
HS_OC: J1.3 ; port HS_OC
HS_PWM: J1.11 ; port HS_PWM
HS_TEMP: J1.2 ; port HS_TEMP
LS_OC: J1.1 ; port LS_OC
LS_PWM: J1.9 ; port LS_PWM
LS_TEMP: J1.4 ; port LS_TEMP
SW: TP3.1 TP6.1 ; port SW

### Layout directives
net class INGND: (no net found under the mark)

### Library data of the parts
J1 = CMP-0120913-1: Manufacturer: Samtec; ContactFinish: Gold,Nickel; Current_A: 3.4A; Row_Count: 2; AEC Qualified: No; Conn Gender: Male; Conn Orientation: Right Angle; DUT-Pitch_mm: 1.27mm; SizeZ_mm: 3.56mm
J2 = CMP-0120912-1: Connector Unshrouded Header HDR 4 POS 1.27mm Solder RA Thru-Hole; Manufacturer: Samtec; ContactFinish: Gold,Nickel; Current_A: 3.4A; Row_Count: 2; AEC Qualified: No; Conn Gender: Male; Conn Orientation: Right Angle; SizeZ_mm: 3.56mm
TP1-TP6 = CMP-0082316-1: PCB Pin, 0.04" DIA, Edge-Mount; Manufacturer: Mill-Max; CompType: PCB Pin; ContactFinish: Gold; Gender: Male; Row_Count: 1

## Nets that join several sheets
5V0: GaN Card (6 pins), GaN Card_Hardware (J1.12)
DGND: GaN Card (30 pins), GaN Card_Hardware (J1.8 J1.10)
HVBUS: GaN Card (18 pins), GaN Card_Hardware (TP1.1 TP4.1)
ISO_12V_L: GaN Card (C11.1 U5.44), GaN Card_Hardware (J2.2)
PGND: GaN Card (36 pins), GaN Card_Hardware (J2.1 J2.3 TP2.1 TP5.1)
EN_DRV: GaN Card (R3.1 R8.2), GaN Card_Hardware (J1.5)
EN_ISO 12V: GaN Card (R4.1 R14.2), GaN Card_Hardware (J1.7)
GaN_FAULT: GaN Card (U6.4), GaN Card_Hardware (J1.6)
HS_OC: GaN Card (C35.1 R23.2), GaN Card_Hardware (J1.3)
HS_PWM: GaN Card (U8.5), GaN Card_Hardware (J1.11)
HS_TEMP: GaN Card (R21.2), GaN Card_Hardware (J1.2)
LS_OC: GaN Card (C32.1 R13.2), GaN Card_Hardware (J1.1)
LS_PWM: GaN Card (U8.1), GaN Card_Hardware (J1.9)
LS_TEMP: GaN Card (R11.2), GaN Card_Hardware (J1.4)
SW: GaN Card (47 pins), GaN Card_Hardware (TP3.1 TP6.1)

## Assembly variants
PMP41126 GaN Card: not fitted R10 R15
